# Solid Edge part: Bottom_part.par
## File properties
Author: Krammer
Template: iso metric part.par
Last saved by: Krammer
Revision: 3
Application: Solid Edge
Accuracy: 0,990
Username: Krammer
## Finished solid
Body 1: solid body, 34 faces, 56 edges, 24 vertices.
  Faces by surface: plane 23, cylinder 10, cone 1
  Edges by curve: line 35, circle 21
Bounding box of the edges (mm): 31.000 x 18.000 x 4.000, from (0, 0, 0) to (31, 18, 4).
Cylindrical faces by radius (mm): R0.75 x7, R2.5 x1, R6 x1, R9 x1
Conical faces (half-angle, radius in mm at the cone's reference point): 45 deg R8.5 x1
Planar faces by outward normal: +y 2, +z 10, -x 1, -y 2, -z 1, oblique 7
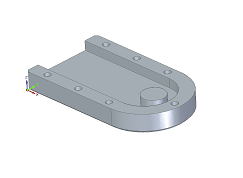
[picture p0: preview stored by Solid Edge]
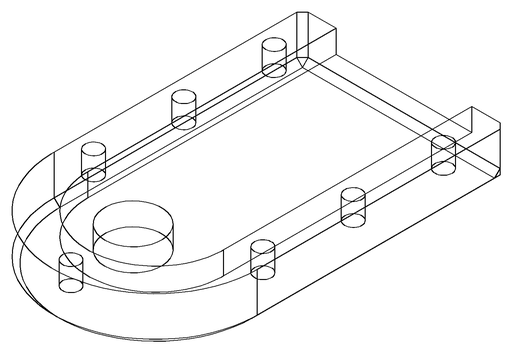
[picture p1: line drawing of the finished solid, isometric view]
